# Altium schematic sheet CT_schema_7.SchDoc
size 252 x 159 mm
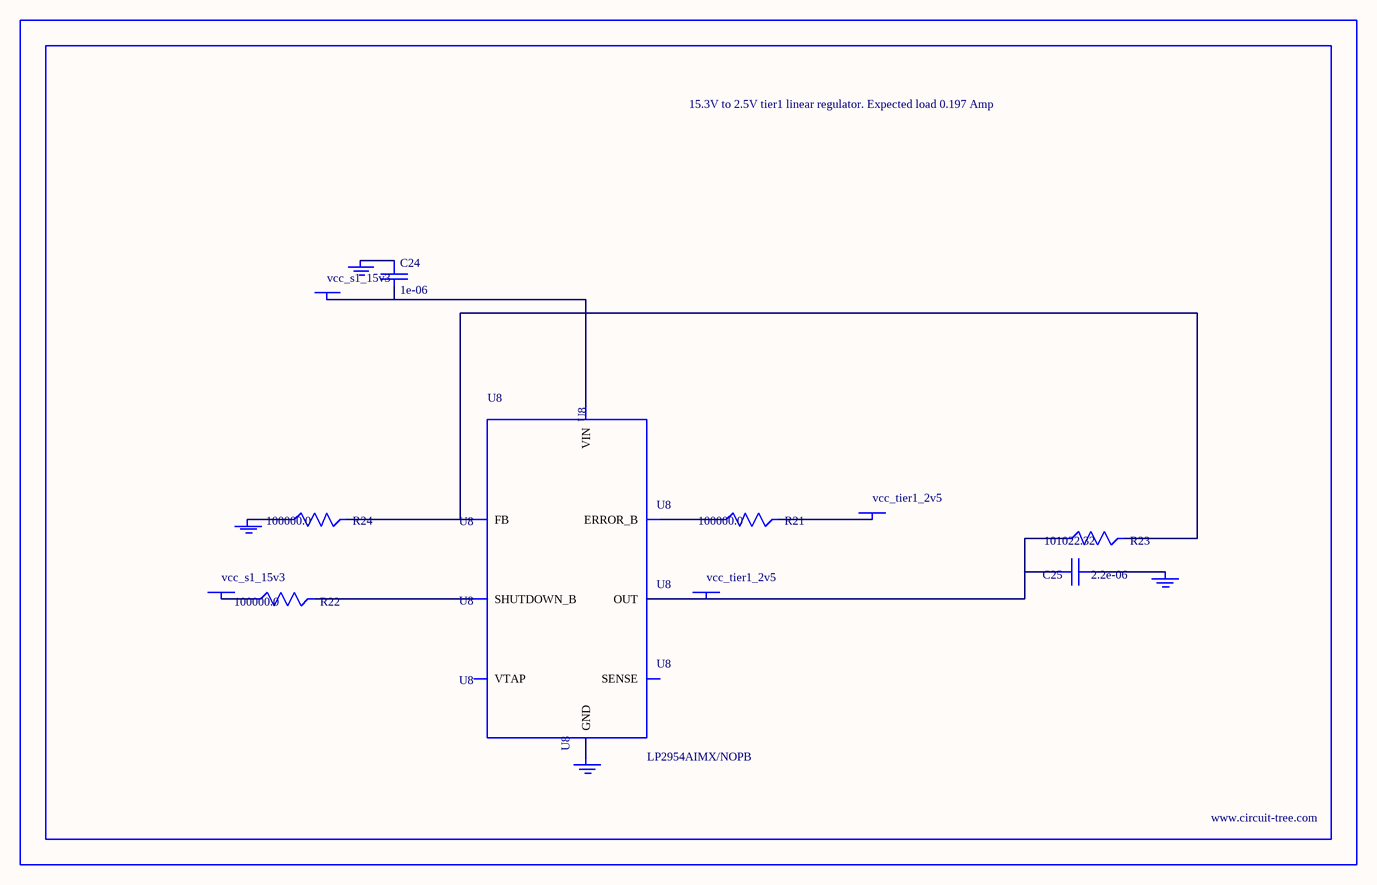
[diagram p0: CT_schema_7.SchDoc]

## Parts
BORDER6  (no value)
C24  1e-06  [EXV-9B]
C25  2.2e-06  [EXV-9B]
GND_INSTANCE_6_0  (no value)
GND_INSTANCE_6_1  (no value)
GND_INSTANCE_6_2  (no value)
GND_INSTANCE_6_3  (no value)
POWER_INSTANCE_6_0  vcc_s1_15v3
POWER_INSTANCE_6_1  vcc_tier1_2v5
POWER_INSTANCE_6_2  vcc_s1_15v3
POWER_INSTANCE_6_3  vcc_tier1_2v5
R21  100000.0  [R0603]
R22  100000.0  [R0603]
R23  101022.32  [R0603]
R24  100000.0  [R0603]
U8  LP2954AIMX/NOPB  [LP2954]

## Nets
NetC24_1: C24.1 GND_INSTANCE_6_2.0(GND)
NetC24_2: C24.2 POWER_INSTANCE_6_2.0(PWR) U8.8(VIN)
NetC25_1: C25.1 GND_INSTANCE_6_0.0(GND)
NetC25_2: C25.2 POWER_INSTANCE_6_3.0(PWR) R23.1 U8.1(OUT)
NetGND_INSTANCE_6_1_0: GND_INSTANCE_6_1.0(GND) R24.1
NetGND_INSTANCE_6_3_0: GND_INSTANCE_6_3.0(GND) U8.4(GND)
NetPOWER_INSTANCE_6_0_0: POWER_INSTANCE_6_0.0(PWR) R22.1
NetPOWER_INSTANCE_6_1_0: POWER_INSTANCE_6_1.0(PWR) R21.2
NetR21_1: R21.1 U8.5(ERROR_B)
NetR22_2: R22.2 U8.3(SHUTDOWN_B)
NetR23_2: R23.2 R24.2 U8.7(FB)

Not connected (* = marked no-connect by the designer): U8 2(SENSE) 6(VTAP)

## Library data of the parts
BORDER6 = BORDER_PAGE6
C24 = EDK105M050A9BAA
C25 = EDK225M050A9BAA
GND_INSTANCE_6_0-GND_INSTANCE_6_3 = GND
POWER_INSTANCE_6_0-POWER_INSTANCE_6_3 = PWR
R21 R22 R24 = RC0603JR-07100KL
R23 = R23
